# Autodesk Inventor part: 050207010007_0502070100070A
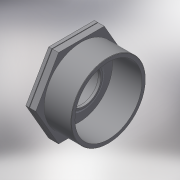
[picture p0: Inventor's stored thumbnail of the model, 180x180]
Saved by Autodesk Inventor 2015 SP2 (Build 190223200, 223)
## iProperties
Created: 2017-05
Part Number: 050207010007_0502070100070A
Material: Generic
Description: PLASSON REDUCING BUSHING 1"-3/4"
Document SubType Name: Modeling
Designer: KIM
Density: 1 g/cm^3
Appearance: Default
Author: KIM
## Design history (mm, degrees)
derived "050207.ipt"
feature "Solid1::050207.ipt"
tag "TaggingFeature1"
body "Solid1"
other parameters: "d1" = 33.249, "d2" = 36, "d5" = 19, "d8" = 0.32, "d12" = 0, "d15" = 32, "d19" = 0, "d30" = 8, "d31" = 4, "d33" = 24.117, "d34" = 29.9241, "d36" = 1.8, "d37" = 27.73455, "d38" = 21.12, "d39" = 21.7053, "d40" = 1.9, "d41" = 0, "H_" = 32, "R_" = 33.249, "E_" = 36, "l_2" = 19, "Rp_" = 24.117
